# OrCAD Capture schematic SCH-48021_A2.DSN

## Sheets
1 1. Title Page: title: FRDMSTBI-NMH1000; rev: A2; company: Freescale Semiconductor; note: SCH-48021 SPF-48021; note: 6501 William Cannon Drive West; note: Austin, TX 78735-8598
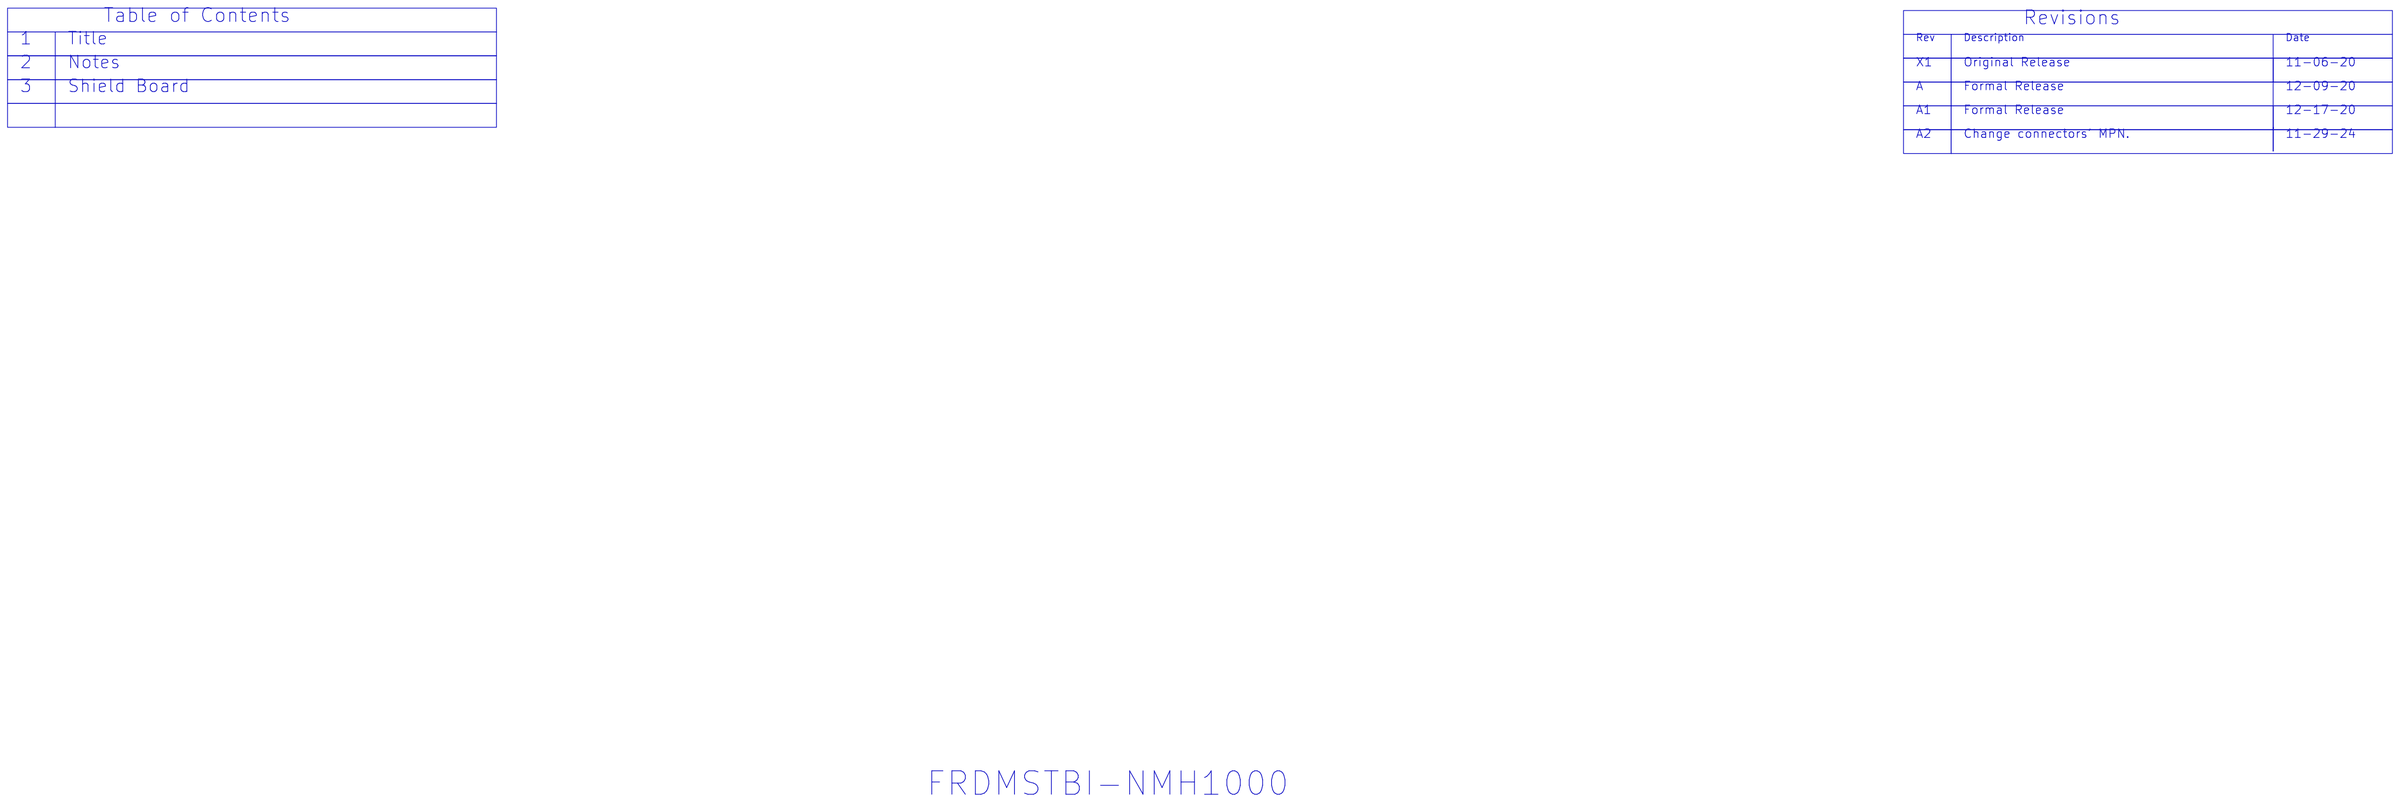
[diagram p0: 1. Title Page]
2 2. Notes
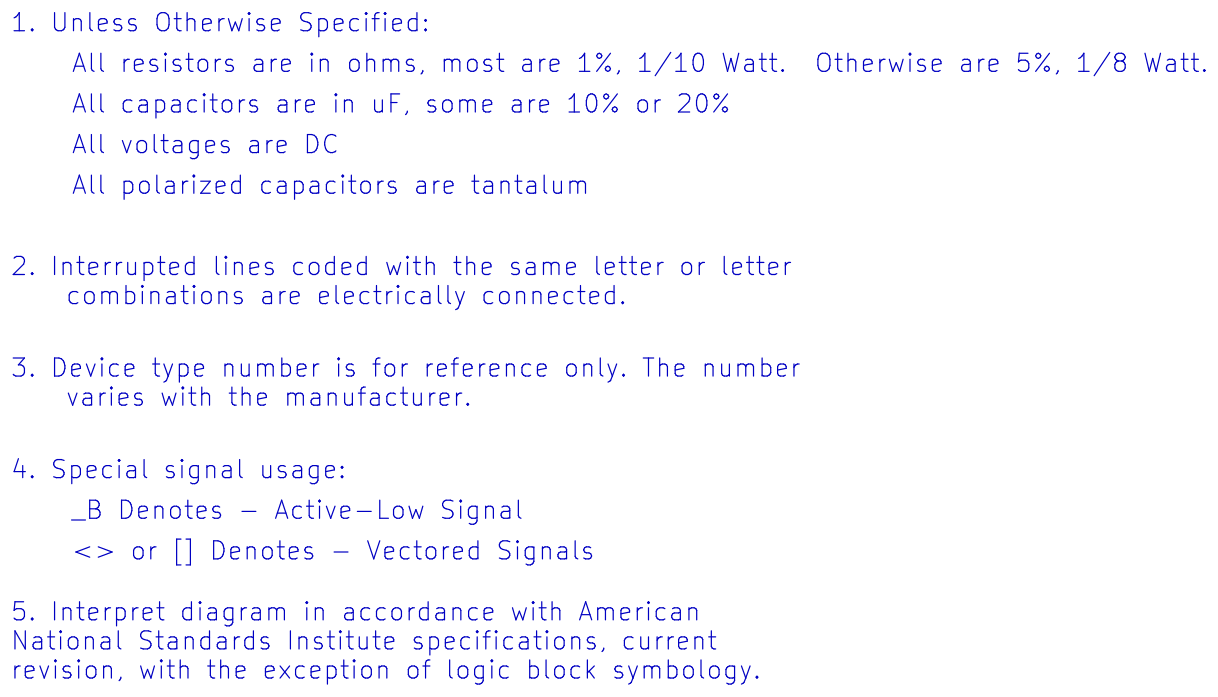
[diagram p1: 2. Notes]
3 3. SHLD BOARD: size C
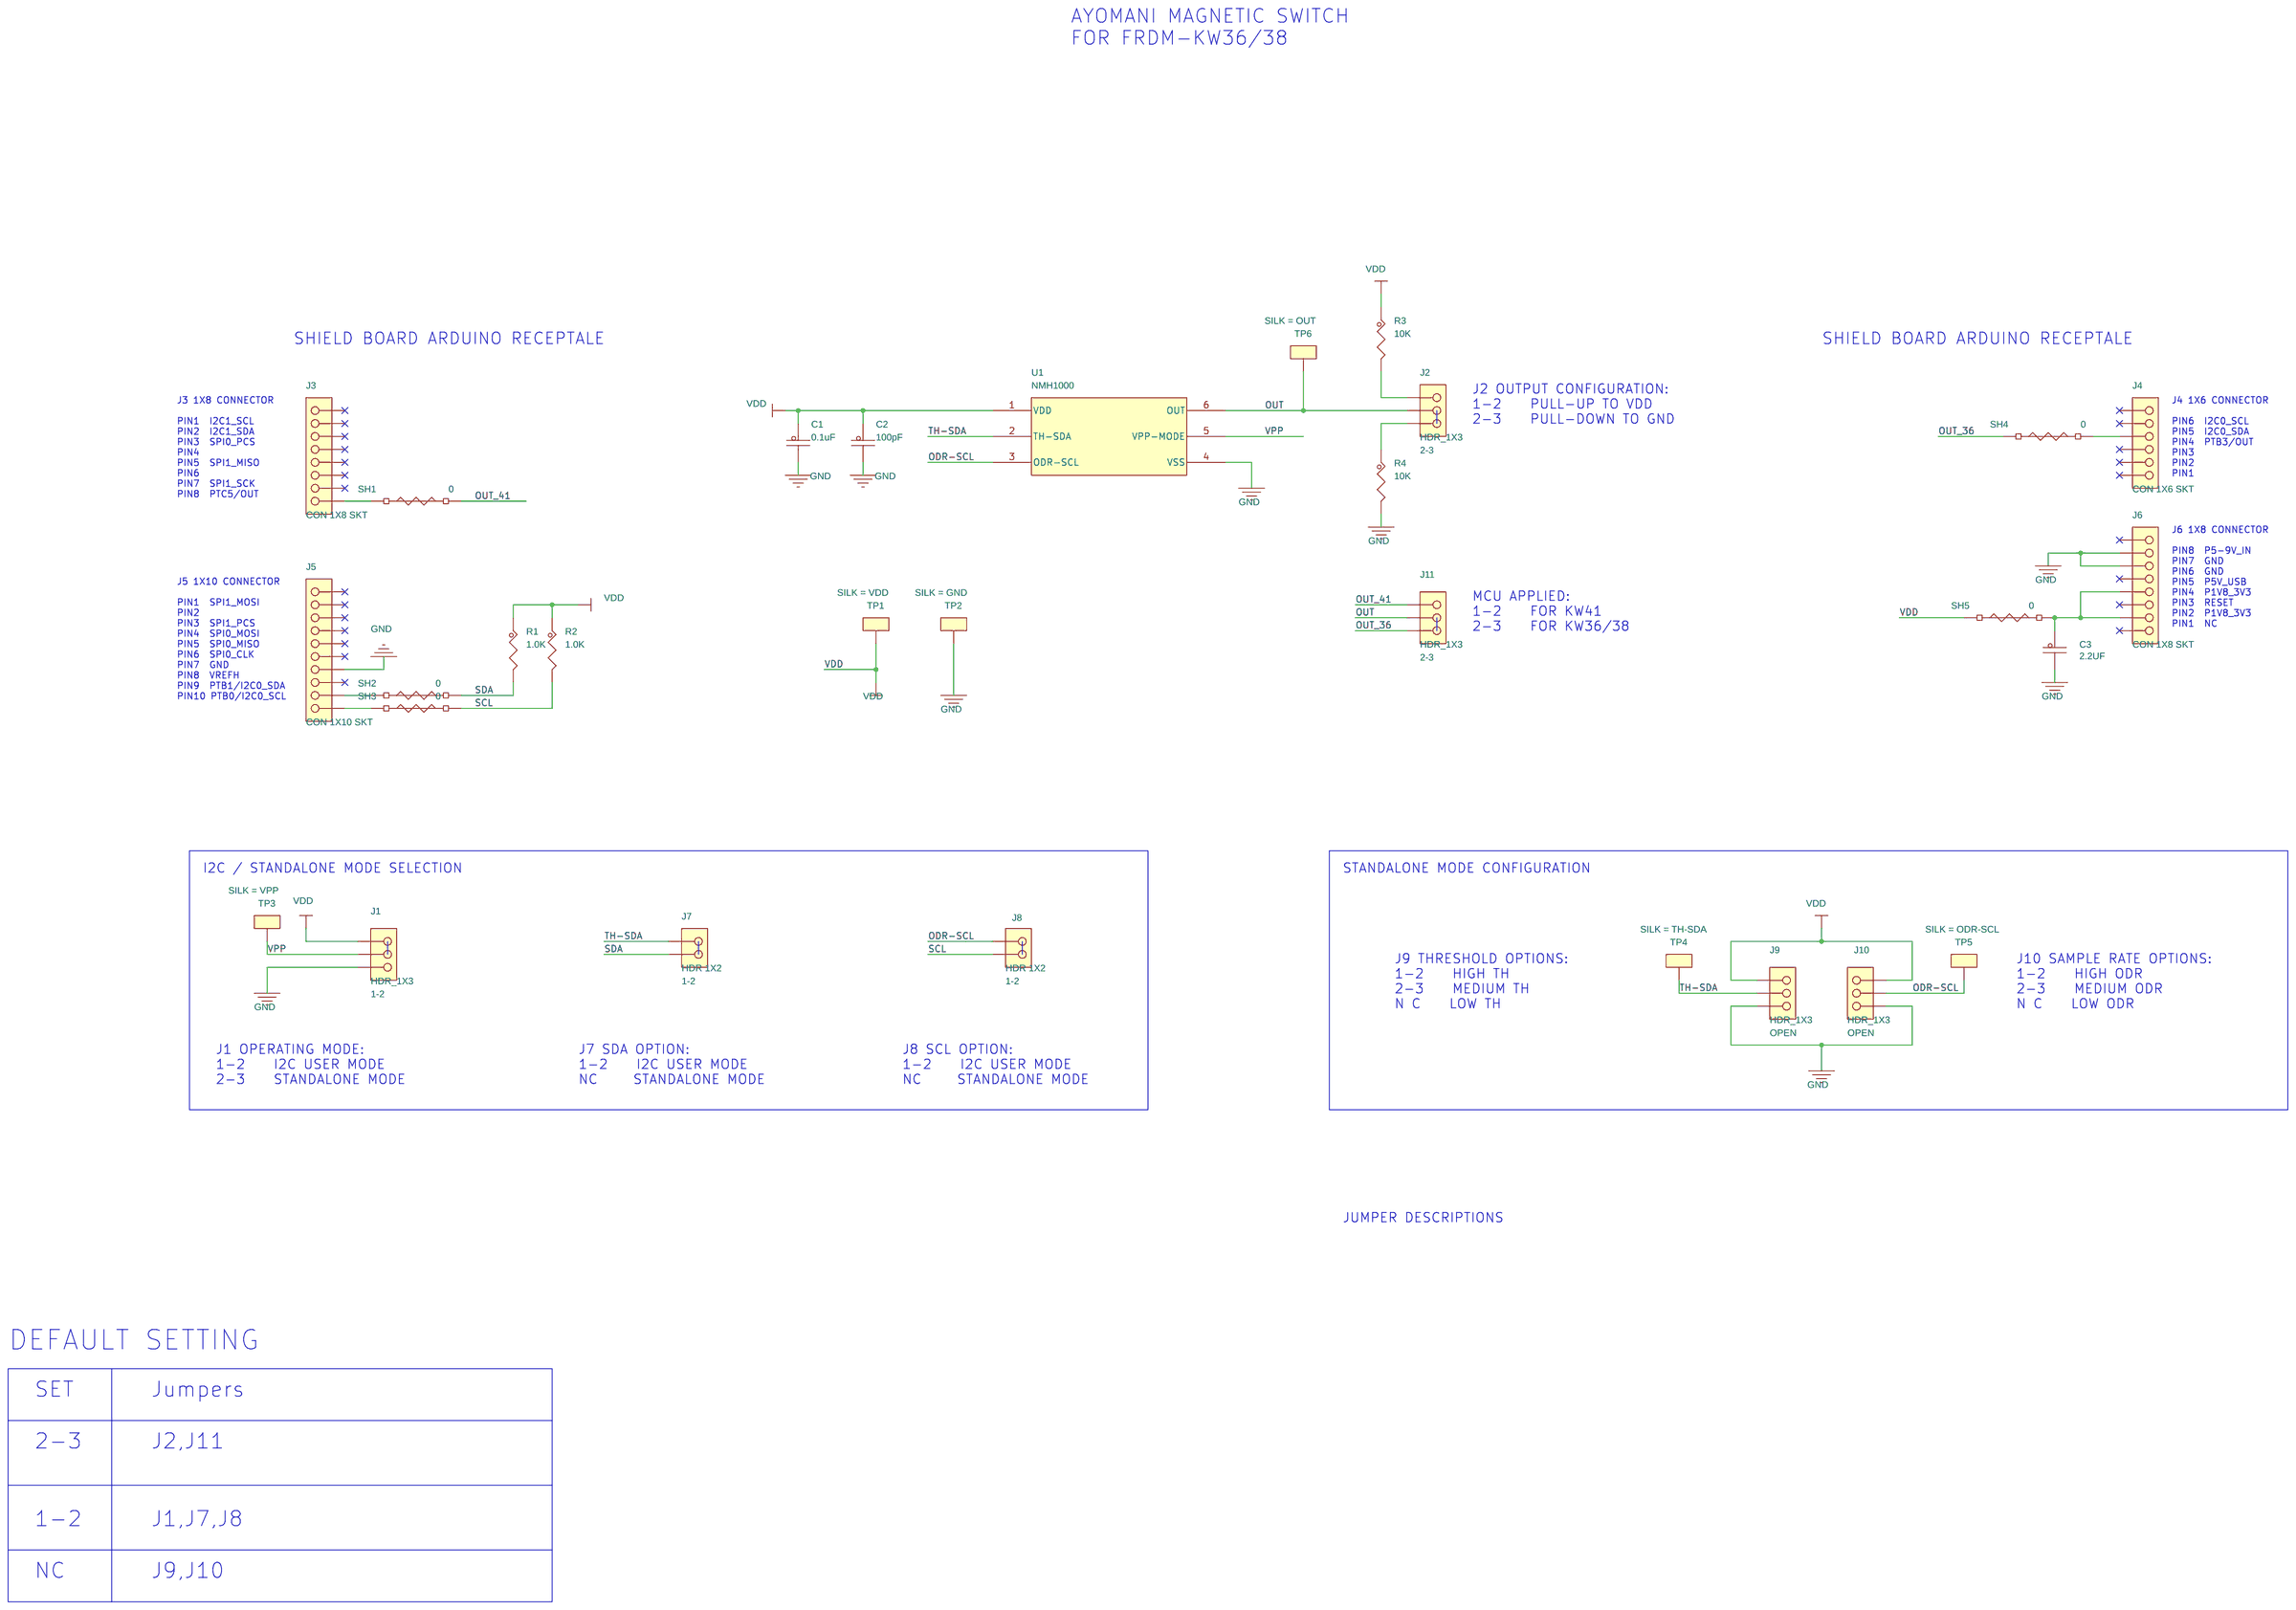
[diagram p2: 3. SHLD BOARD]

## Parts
C1  0.1uF  [CC0402_25]
C2  100pF  [CC0402_25]
C3  2.2UF  [CC0402_25]
J1  HDR_1X3  [hdr103_330h]
J2  HDR_1X3  [hdr103_330h]
J3  CON 1X8 SKT  [con_skt1x8_th_394l]
J4  CON 1X6 SKT  [con_skt1x6_th_394l]
J5  CON 1X10 SKT  [hdr_1x10_2p54_341h]
J6  CON 1X8 SKT  [con_skt1x8_th_394l]
J7  HDR 1X2  [hdr102_95l]
J8  HDR 1X2  [hdr102_95l]
J9  HDR_1X3  [hdr103_330h]
J10  HDR_1X3  [hdr103_330h]
J11  HDR_1X3  [hdr103_330h]
R1  1.0K  [RC0603_OV]
R2  1.0K  [RC0603_OV]
R3  10K  [RC0603_OV]
R4  10K  [RC0603_OV]
SH1  0  [SH0201]
SH2  0  [SH0201]
SH3  0  [SH0201]
SH4  0  [SH0201]
SH5  0  [SH0201]
TP1  0805  [testpoint_122x049mil]
TP2  0805  [testpoint_122x049mil]
TP3  0805  [testpoint_122x049mil]
TP4  0805  [testpoint_122x049mil]
TP5  0805  [testpoint_122x049mil]
TP6  0805  [testpoint_122x049mil]
U1  NMH1000  [dfn6_0p5_1p4sq]

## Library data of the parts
C1 = CAP_NP: CAP CER 0.1uF 6.3V 10% X7R 0402; AGILE_PN: 150-78678; CAD_APPROVED: Yes; FPLIST: CC0402_25,CC0402_HD,0402_CC; HEIGHT: 0.55; MFG_NAME01: KEMET; MFG_PN01: C0402C104K9RACTU; Package Size: 0402; Package Type: Tape & reel; ROHS: Yes; Rated Voltage: 6.3V; TOL: 10%; Temp Range: -55C to +125C; Tolerance: 10%; VOLTAGE: 6.3V
C2 = CAP_NP: CAP CER 100pF 50V 5% C0G AEC-Q200 0402; AGILE_PN: 150-79021; CAD_APPROVED: Yes; FPLIST: CC0402_25,CC0402_HD,0402_CC; HEIGHT: 0.55MM; MFG_NAME01: MURATA; MFG_PN01: GCM1555C1H101JA16B; Package Size: 0402; Package Type: Bulk Bag; ROHS: NULL; Rated Voltage: 50V; TOL: 5%; Temp Range: -55C to +125C; Tolerance: 5%; VOLTAGE: 50V
C3 = CAP_NP: CAP CER 2.2UF 6.3V 20% X5R 0402; AGILE_PN: 150-76792; CAD_APPROVED: Yes; FPLIST: CC0402_25,CC0402_HD,0402_CC; HEIGHT: 0.55; MFG_NAME01: KEMET; MFG_PN01: C0402C225M9PACTU; Package Size: 0402; ROHS: Yes; Rated Voltage: 6.3V; Temp Range: -55C to +85C; Tolerance: 20%; VOLTAGE: 6.3V
J1 = CONN_HDR_3X1: HDR 1X3 TH 100MIL SP 338H AU 98L; 3D_Mechanical_Footprint_File: http://fcl.am.freescale.net/ALLEGRO/step/hdr103_330h.STEP; AGILE_PN: 210-81491; CAD_APPROVED: Yes; FPLIST: hdr103_330h,HDR103,sh_hdr103_bottom_12,sh_hdr103_bottom_23; HEIGHT: 8.59; JUMPER[DEFAULT]: 1-2; MFG_NAME01: ANYTRONIC CORPORATION LIMITED; MFG_PN01: 0901S0203011N9T-31RF; ROHS: Yes; Temp Range: -55°C to +105°C
J2 J11 = CONN_HDR_3X1: HDR 1X3 TH 100MIL SP 338H AU 98L; 3D_Mechanical_Footprint_File: http://fcl.am.freescale.net/ALLEGRO/step/hdr103_330h.STEP; AGILE_PN: 210-81491; CAD_APPROVED: Yes; FPLIST: hdr103_330h,HDR103,sh_hdr103_bottom_12,sh_hdr103_bottom_23; HEIGHT: 8.59; JUMPER[DEFAULT]: 2-3; MFG_NAME01: ANYTRONIC CORPORATION LIMITED; MFG_PN01: 0901S0203011N9T-31RF; ROHS: Yes; Temp Range: -55°C to +105°C
J3 J6 = CONN_HDR_8X1: CON 1X8 SKT SHRD TH 100MIL SP 343H AU 392L; 3D_Mechanical_Footprint_File: http://fcl.am.freescale.net/ALLEGRO/step/con_skt1x8_th_394l.STEP; AGILE_PN: 210-10329; Contact Voltage: 250V; HEIGHT: 8.7mm; MFG_NAME01: TOWNES ENTERPRICE CO.,LTD; MFG_PN01: F209-1*08SGF-0A-NH; Package Size: 20.82 x 2.54 mm; Package Type: PCB, Through Hole; ROHS: NULL; Temp Range: -25°C to 105°C
J4 = CONN_HDR_6X1: CON 1X6 SKT SHRD TH 100MIL SP 343H AU 392L; 3D_Mechanical_Footprint_File: http://fcl.am.freescale.net/ALLEGRO/step/con_skt1x6_th_394l.STEP; AGILE_PN: 210-10331; Contact Voltage: 250V; HEIGHT: 8.7mm; MFG_NAME01: TOWNES ENTERPRICE CO.,LTD; MFG_PN01: F209-1*06SGF-0A-NH; Package Size: 15.74 x 2.54 mm; Package Type: PCB, Through Hole; ROHS: NULL; Temp Range: -25°C to 105°C
J5 = CONN_HDR_10X1: CON 1X10 SKT SHRD TH 100MIL SP 341H AU 392L; 3D_Mechanical_Footprint_File: http://fcl.am.freescale.net/ALLEGRO/step/hdr_1x10_2p54_341h.STEP; AGILE_PN: 210-10330; CAD_APPROVED: Yes; Contact Voltage: 250 V AC/DC; HEIGHT: 8.65; MFG_NAME01: TOWNES ENTERPRICE CO.,LTD; MFG_PN01: F209-1*10SGF-0A-NH; Package Size: 25.9 x 2.54 mm; Package Type: Through Hole; ROHS: NULL; Temp Range: -25°C to 105°C
J7 J8 = CONN_HDR_2X1: HDR 1X2 TH 100MIL SP 339H AU 98L; 3D_Mechanical_Footprint_File: http://fcl.am.freescale.net/ALLEGRO/step/hdr102_95l.STEP; AGILE_PN: 210-81490; CAD_APPROVED: Yes; FPLIST: hdr102_95l,HDR102; HEIGHT: 8.59; JUMPER[DEFAULT]: 1-2; MFG_NAME01: ANYTRONIC CORPORATION LIMITED; MFG_PN01: 0901S0202011N9T-31RF; ROHS: Yes; Temp Range: -55°C to +105°C
J9 J10 = CONN_HDR_3X1: HDR 1X3 TH 100MIL SP 338H AU 98L; 3D_Mechanical_Footprint_File: http://fcl.am.freescale.net/ALLEGRO/step/hdr103_330h.STEP; AGILE_PN: 210-81491; CAD_APPROVED: Yes; FPLIST: hdr103_330h,HDR103,sh_hdr103_bottom_12,sh_hdr103_bottom_23; HEIGHT: 8.59; JUMPER[DEFAULT]: OPEN; MFG_NAME01: ANYTRONIC CORPORATION LIMITED; MFG_PN01: 0901S0203011N9T-31RF; ROHS: Yes; Temp Range: -55°C to +105°C
R1 R2 = RES: RES MF 1.00K 1/10W 1% 0603; AGILE_PN: 470-75421; CAD_APPROVED: Yes; FPLIST: RC0603_OV,RC0603,0603_CC; HEIGHT: 0.55; MFG_NAME01: BOURNS; MFG_PN01: CR0603-FX-1001ELF; ROHS: Yes; Tolerance: 1%
R3 R4 = RES: RES MF 10K 1/10W 5% 0603; AGILE_PN: 470-75410; CAD_APPROVED: Yes; FPLIST: RC0603_OV,RC0603,0603_CC,r603-x2; HEIGHT: 0.55; MFG_NAME01: BOURNS; MFG_PN01: CR0603-JW-103ELF; ROHS: Yes; Temp Range: –55 °C to +155 °C; Tolerance: 5%
SH1-SH5 = RES_SHORT-2: ZERO OHM CUT TRACE 0201 PADS; NO PART TO ORDER; AGILE_PN: 470-76473; CAD_APPROVED: Yes; FPLIST: SH0201,SH0201_CC; HEIGHT: 0.1; ROHS: Yes
TP1 = TEST_POINT: TEST POINT PAD 3.1MMX1.25MM SMT AEC-Q200 0805; 3D_Mechanical_Footprint_File: http://fcl.am.freescale.net/ALLEGRO/step/testpoint_122x049mil.STEP; AGILE_PN: 211-79608; CAD_APPROVED: Yes; HEIGHT: 1.45; MFG_NAME01: KOA SPEER; MFG_PN01: RCTCTE; Package Size: 2X1.25x1.45MM; Package Type: SMT; ROHS: Yes; SILK: VDD
TP2 = TEST_POINT: TEST POINT PAD 3.1MMX1.25MM SMT AEC-Q200 0805; 3D_Mechanical_Footprint_File: http://fcl.am.freescale.net/ALLEGRO/step/testpoint_122x049mil.STEP; AGILE_PN: 211-79608; CAD_APPROVED: Yes; HEIGHT: 1.45; MFG_NAME01: KOA SPEER; MFG_PN01: RCTCTE; Package Size: 2X1.25x1.45MM; Package Type: SMT; ROHS: Yes; SILK: GND
TP3 = TEST_POINT: TEST POINT PAD 3.1MMX1.25MM SMT AEC-Q200 0805; 3D_Mechanical_Footprint_File: http://fcl.am.freescale.net/ALLEGRO/step/testpoint_122x049mil.STEP; AGILE_PN: 211-79608; CAD_APPROVED: Yes; HEIGHT: 1.45; MFG_NAME01: KOA SPEER; MFG_PN01: RCTCTE; Package Size: 2X1.25x1.45MM; Package Type: SMT; ROHS: Yes; SILK: VPP
TP4 = TEST_POINT: TEST POINT PAD 3.1MMX1.25MM SMT AEC-Q200 0805; 3D_Mechanical_Footprint_File: http://fcl.am.freescale.net/ALLEGRO/step/testpoint_122x049mil.STEP; AGILE_PN: 211-79608; CAD_APPROVED: Yes; HEIGHT: 1.45; MFG_NAME01: KOA SPEER; MFG_PN01: RCTCTE; Package Size: 2X1.25x1.45MM; Package Type: SMT; ROHS: Yes; SILK: TH-SDA
TP5 = TEST_POINT: TEST POINT PAD 3.1MMX1.25MM SMT AEC-Q200 0805; 3D_Mechanical_Footprint_File: http://fcl.am.freescale.net/ALLEGRO/step/testpoint_122x049mil.STEP; AGILE_PN: 211-79608; CAD_APPROVED: Yes; HEIGHT: 1.45; MFG_NAME01: KOA SPEER; MFG_PN01: RCTCTE; Package Size: 2X1.25x1.45MM; Package Type: SMT; ROHS: Yes; SILK: ODR-SCL
TP6 = TEST_POINT: TEST POINT PAD 3.1MMX1.25MM SMT AEC-Q200 0805; 3D_Mechanical_Footprint_File: http://fcl.am.freescale.net/ALLEGRO/step/testpoint_122x049mil.STEP; AGILE_PN: 211-79608; CAD_APPROVED: Yes; HEIGHT: 1.45; MFG_NAME01: KOA SPEER; MFG_PN01: RCTCTE; Package Size: 2X1.25x1.45MM; Package Type: SMT; ROHS: Yes; SILK: OUT
U1 = NMH1000_6P: IC SENSOR Z-AXIC MAGNETIC SW 1.2-3.6V PDFN6; 3D_Mechanical_Footprint_File: http://fcl.am.freescale.net/ALLEGRO/step/dfn6_0p5_1p4sq.STEP; AGILE_PN: TMP-CIP-6445; CAD_APPROVED: Yes; HEIGHT: 0.9; MFG_NAME01: NXP SEMICONDUCTORS; PRE_APN: 312-83057; Package Size: 1.4x1.4x0.9 mm; ROHS: Yes; Temp Range: -40°C  to +85°C; VOLTAGE: 1.2-3.6V

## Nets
GND: C1.2 C2.2 C3.2 J1.3 J5.7 J6.6 J6.7 J9.3 J10.3 R4.2 TP2.1 U1.4(VSS)
VDD: C1.1 C2.1 J1.1 J9.1 J10.1 R1.1 R2.1 R3.1 SH5.1 TP1.1 U1.1(VDD)
ODR-SCL: J8.1 J10.2 TP5.1 U1.3(ODR-SCL)
OUT: J2.2 J11.2 TP6.1 U1.6(OUT)
OUT_36: J11.3 SH4.2
OUT_41: J11.1 SH1.1
SCL: J8.2 R2.2 SH3.2
SDA: J7.2 R1.2 SH2.2
TH-SDA: J7.1 J9.2 TP4.1 U1.2(TH-SDA)
VPP: J1.2 TP3.1 U1.5(VPP-MODE)
N16711572: J3.8 SH1.2
N16711688: J5.9 SH2.1
N16711714: J5.10 SH3.1
N16711987: J4.4 SH4.1
N16712049: C3.1 J6.2 J6.4 SH5.2
N16714153: J2.1 R3.2
N16714249: J2.3 R4.1

Not connected (* = marked no-connect by the designer): J3 1* 2* 3* 4* 5* 6* 7*; J4 1* 2* 3* 5* 6*; J5 1* 2* 3* 4* 5* 6* 8*; J6 1* 3* 5* 8*

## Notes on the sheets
sheet 1
- Table of Contents
- Revisions
- 1
- Title
- Rev
- Description
- Date
- 2
- Notes
- X1
- Original Release
- 11-06-20
- 3
- Shield Board
- A
- Formal Release
- 12-09-20
- A1
- Formal Release
- 12-17-20
- A2
- Change connectors' MPN.
- 11-29-24
- FRDMSTBI-NMH1000
sheet 2
- 1. Unless Otherwise Specified:
- All resistors are in ohms, most are 1%, 1/10 Watt.  Otherwise are 5%, 1/8 Watt.
- All capacitors are in uF, some are 10% or 20%
- All voltages are DC
- All polarized capacitors are tantalum
- 2. Interrupted lines coded with the same letter or letter
      combinations are electrically connected.
- 3. Device type number is for reference only. The number
      varies with the manufacturer.
- 4. Special signal usage:
- _B Denotes - Active-Low Signal
- <> or [] Denotes - Vectored Signals
- 5. Interpret diagram in accordance with American
  National Standards Institute specifications, current
  revision, with the exception of logic block symbology.
sheet 3
- AYOMANI MAGNETIC SWITCH
  FOR FRDM-KW36/38
- SHIELD BOARD ARDUINO RECEPTALE
- SHIELD BOARD ARDUINO RECEPTALE
- J2 OUTPUT CONFIGURATION:
  1-2    PULL-UP TO VDD
  2-3    PULL-DOWN TO GND
- J3 1X8 CONNECTOR
  PIN1  I2C1_SCL
  PIN2  I2C1_SDA
  PIN3  SPI0_PCS
  PIN4
  PIN5  SPI1_MISO
  PIN6
  PIN7  SPI1_SCK
  PIN8  PTC5/OUT
- J4 1X6 CONNECTOR
  PIN6  I2C0_SCL
  PIN5  I2C0_SDA
  PIN4  PTB3/OUT
  PIN3
  PIN2
  PIN1
- J6 1X8 CONNECTOR
  PIN8  P5-9V_IN
  PIN7  GND
  PIN6  GND
  PIN5  P5V_USB
  PIN4  P1V8_3V3
  PIN3  RESET
  PIN2  P1V8_3V3
  PIN1  NC
- J5 1X10 CONNECTOR
  PIN1  SPI1_MOSI
  PIN2
  PIN3  SPI1_PCS
  PIN4  SPI0_MOSI
  PIN5  SPI0_MISO
  PIN6  SPI0_CLK
  PIN7  GND
  PIN8  VREFH
  PIN9  PTB1/I2C0_SDA
  PIN10 PTB0/I2C0_SCL
- MCU APPLIED:
  1-2    FOR KW41
  2-3    FOR KW36/38
- I2C / STANDALONE MODE SELECTION
- STANDALONE MODE CONFIGURATION
- J9 THRESHOLD OPTIONS:
  1-2    HIGH TH
  2-3    MEDIUM TH
  N C    LOW TH
- J10 SAMPLE RATE OPTIONS:
  1-2    HIGH ODR
  2-3    MEDIUM ODR
  N C    LOW ODR
- J1 OPERATING MODE:
  1-2    I2C USER MODE
  2-3    STANDALONE MODE
- J7 SDA OPTION:
  1-2    I2C USER MODE
  NC     STANDALONE MODE
- J8 SCL OPTION:
  1-2    I2C USER MODE
  NC     STANDALONE MODE
- JUMPER DESCRIPTIONS
- DEFAULT SETTING
- SET
- Jumpers
- 2-3
- J2,J11
- 1-2
- J1,J7,J8
- NC
- J9,J10
